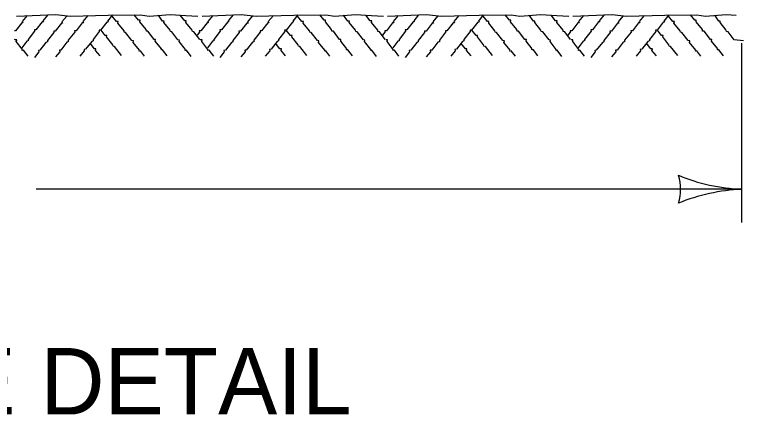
# Model space of a CAD drawing. Extents: x 49991.4 to 50022.1, y 49985 to 50011.4.
# Drawn here: x 50005.452 to 50006.329, y 49996.72 to 49997.202 of the extents above; entities that cross this region are included whole.
import ezdxf

# ---------------------------------------------------------------- set-up
doc = ezdxf.new("R2010")
doc.units = 0
for name, color, linetype in [('Level 1', 7, 'Continuous'), ('Level 2', 7, 'Continuous'), ('Level 3', 7, 'Continuous')]:
    doc.layers.add(name, color=color, linetype=linetype)

msp = doc.modelspace()

# ---------------------------------------------------------------- linework, layer by layer
at = {"layer": 'Level 1'}
for points in [[(50005.4675, 49997.2012), (50005.4615, 49997.1941), (50005.4623, 49997.1926), (50005.4609, 49997.1926), (50005.4535, 49997.183), (50005.4523, 49997.183)], [(50005.4545, 49997.2006), (50005.5017, 49997.2025), (50005.5195, 49997.2004), (50005.5649, 49997.2019), (50005.6037, 49997.2022), (50005.6141, 49997.2007), (50005.6393, 49997.2025), (50005.6584, 49997.2013), (50005.6729, 49997.2006)], [(50005.4921, 49997.202), (50005.4863, 49997.195), (50005.4869, 49997.1936), (50005.4855, 49997.1936), (50005.4779, 49997.184), (50005.4761, 49997.184), (50005.4763, 49997.1824), (50005.4687, 49997.1726), (50005.4687, 49997.171), (50005.467, 49997.1704), (50005.461, 49997.1626)], [(50005.5149, 49997.2004), (50005.5091, 49997.1936), (50005.5099, 49997.1923), (50005.5085, 49997.1923), (50005.5011, 49997.1827), (50005.4993, 49997.1827), (50005.4994, 49997.181), (50005.4917, 49997.1713), (50005.4917, 49997.1696), (50005.4899, 49997.1689), (50005.4827, 49997.1596), (50005.4809, 49997.1593), (50005.4814, 49997.1576), (50005.476, 49997.151)], [(50005.5405, 49997.2012), (50005.5345, 49997.1941), (50005.5353, 49997.1926), (50005.5337, 49997.1926), (50005.5264, 49997.183), (50005.5243, 49997.183), (50005.5247, 49997.1812), (50005.5169, 49997.1718), (50005.5169, 49997.1698), (50005.5153, 49997.1692), (50005.5079, 49997.1598), (50005.5061, 49997.1598), (50005.5065, 49997.1578), (50005.5013, 49997.1515)], [(50005.5699, 49997.202), (50005.5641, 49997.1947), (50005.5648, 49997.1935), (50005.5633, 49997.1935), (50005.5558, 49997.1839), (50005.554, 49997.1839), (50005.5541, 49997.1822), (50005.5467, 49997.1726), (50005.5467, 49997.1707), (50005.545, 49997.1702), (50005.5377, 49997.1608), (50005.5359, 49997.1606), (50005.5361, 49997.1587), (50005.5309, 49997.1524)], [(50005.6085, 49997.1524), (50005.6037, 49997.1587), (50005.6021, 49997.1584), (50005.6025, 49997.1598), (50005.5948, 49997.169), (50005.5954, 49997.171), (50005.5935, 49997.1712), (50005.5859, 49997.1808), (50005.5841, 49997.1812), (50005.584, 49997.183), (50005.5765, 49997.1922), (50005.5767, 49997.1941), (50005.575, 49997.1941), (50005.5697, 49997.2006)], [(50005.6357, 49997.153), (50005.6303, 49997.1602), (50005.6289, 49997.1599), (50005.629, 49997.1612), (50005.6215, 49997.1706), (50005.6219, 49997.1725), (50005.6201, 49997.1726), (50005.6125, 49997.1824), (50005.6109, 49997.1827), (50005.6105, 49997.1845), (50005.6029, 49997.1936), (50005.6033, 49997.1956), (50005.6014, 49997.1956), (50005.5963, 49997.202)], [(50005.6649, 49997.1522), (50005.6591, 49997.1596), (50005.6577, 49997.1592), (50005.6578, 49997.1605), (50005.6503, 49997.1701), (50005.6507, 49997.1718), (50005.6489, 49997.172), (50005.6413, 49997.1816), (50005.6397, 49997.1821), (50005.6395, 49997.1838), (50005.6319, 49997.193), (50005.6321, 49997.1947), (50005.6303, 49997.1947), (50005.6253, 49997.2016)], [(50005.6753, 49997.1726), (50005.6681, 49997.1816), (50005.6663, 49997.1822), (50005.6661, 49997.1839), (50005.6585, 49997.193), (50005.6589, 49997.195), (50005.6571, 49997.195), (50005.6517, 49997.2019)], [(50005.6908, 49997.2012), (50005.6848, 49997.1941), (50005.6854, 49997.1926), (50005.6841, 49997.1926), (50005.6765, 49997.183), (50005.6757, 49997.183)], [(50005.6779, 49997.2006), (50005.725, 49997.2025), (50005.7429, 49997.2004), (50005.7883, 49997.2019), (50005.8269, 49997.2022), (50005.8375, 49997.2007), (50005.8624, 49997.2025), (50005.8817, 49997.2013), (50005.8963, 49997.2006)], [(50005.7154, 49997.202), (50005.7094, 49997.195), (50005.7101, 49997.1936), (50005.7087, 49997.1936), (50005.7013, 49997.184), (50005.6993, 49997.184), (50005.6997, 49997.1824), (50005.692, 49997.1726), (50005.692, 49997.171), (50005.6903, 49997.1704), (50005.6843, 49997.1626)], [(50005.7381, 49997.2004), (50005.7325, 49997.1936), (50005.7333, 49997.1923), (50005.7317, 49997.1923), (50005.7243, 49997.1827), (50005.7223, 49997.1827), (50005.7227, 49997.181), (50005.7149, 49997.1713), (50005.7149, 49997.1696), (50005.7133, 49997.1689), (50005.7059, 49997.1596), (50005.7041, 49997.1593), (50005.7045, 49997.1576), (50005.6993, 49997.151)], [(50005.7639, 49997.2012), (50005.7575, 49997.1941), (50005.7583, 49997.1926), (50005.7569, 49997.1926), (50005.7495, 49997.183), (50005.7477, 49997.183), (50005.7478, 49997.1812), (50005.7401, 49997.1718), (50005.7401, 49997.1698), (50005.7385, 49997.1692), (50005.7311, 49997.1598), (50005.7295, 49997.1598), (50005.7298, 49997.1578), (50005.7244, 49997.1515)], [(50005.7933, 49997.202), (50005.7873, 49997.1947), (50005.788, 49997.1935), (50005.7867, 49997.1935), (50005.7791, 49997.1839), (50005.7773, 49997.1839), (50005.7775, 49997.1822), (50005.7699, 49997.1726), (50005.7699, 49997.1707), (50005.7681, 49997.1702), (50005.7609, 49997.1608), (50005.7591, 49997.1606), (50005.7593, 49997.1587), (50005.7539, 49997.1524)], [(50005.8317, 49997.1524), (50005.827, 49997.1587), (50005.8255, 49997.1584), (50005.8257, 49997.1598), (50005.8181, 49997.169), (50005.8185, 49997.171), (50005.8167, 49997.1712), (50005.8091, 49997.1808), (50005.8075, 49997.1812), (50005.8071, 49997.183), (50005.7995, 49997.1922), (50005.8, 49997.1941), (50005.7981, 49997.1941), (50005.7929, 49997.2006)], [(50005.8589, 49997.153), (50005.8534, 49997.1602), (50005.8519, 49997.1599), (50005.8523, 49997.1612), (50005.8449, 49997.1706), (50005.8451, 49997.1725), (50005.8433, 49997.1726), (50005.8359, 49997.1824), (50005.8341, 49997.1827), (50005.8337, 49997.1845), (50005.8263, 49997.1936), (50005.8264, 49997.1956), (50005.8247, 49997.1956), (50005.8195, 49997.202)], [(50005.8879, 49997.1522), (50005.8823, 49997.1596), (50005.8809, 49997.1592), (50005.8811, 49997.1605), (50005.8735, 49997.1701), (50005.8739, 49997.1718), (50005.8721, 49997.172), (50005.8647, 49997.1816), (50005.8629, 49997.1821), (50005.8625, 49997.1838), (50005.8551, 49997.193), (50005.8555, 49997.1947), (50005.8535, 49997.1947), (50005.8483, 49997.2016)], [(50005.8984, 49997.1726), (50005.8913, 49997.1816), (50005.8895, 49997.1822), (50005.8894, 49997.1839), (50005.8817, 49997.193), (50005.8821, 49997.195), (50005.8803, 49997.195), (50005.875, 49997.2019)], [(50005.914, 49997.2012), (50005.908, 49997.1941), (50005.9087, 49997.1926), (50005.9073, 49997.1926), (50005.8997, 49997.183), (50005.8989, 49997.183)], [(50005.9009, 49997.2006), (50005.9481, 49997.2025), (50005.9659, 49997.2004), (50006.0115, 49997.2019), (50006.0499, 49997.2022), (50006.0605, 49997.2007), (50006.0855, 49997.2025), (50006.1048, 49997.2013), (50006.1195, 49997.2006)], [(50005.9385, 49997.202), (50005.9327, 49997.195), (50005.9333, 49997.1936), (50005.932, 49997.1936), (50005.9245, 49997.184), (50005.9225, 49997.184), (50005.9229, 49997.1824), (50005.9151, 49997.1726), (50005.9151, 49997.171), (50005.9134, 49997.1704), (50005.9074, 49997.1626)], [(50005.9613, 49997.2004), (50005.9555, 49997.1936), (50005.9563, 49997.1923), (50005.9548, 49997.1923), (50005.9475, 49997.1827), (50005.9457, 49997.1827), (50005.9458, 49997.181), (50005.9381, 49997.1713), (50005.9381, 49997.1696), (50005.9365, 49997.1689), (50005.9291, 49997.1596), (50005.9273, 49997.1593), (50005.9277, 49997.1576), (50005.9224, 49997.151)], [(50005.9869, 49997.2012), (50005.9809, 49997.1941), (50005.9817, 49997.1926), (50005.9801, 49997.1926), (50005.9727, 49997.183), (50005.9709, 49997.183), (50005.971, 49997.1812), (50005.9635, 49997.1718), (50005.9635, 49997.1698), (50005.9615, 49997.1692), (50005.9545, 49997.1598), (50005.9525, 49997.1598), (50005.953, 49997.1578), (50005.9477, 49997.1515)], [(50006.0163, 49997.202), (50006.0105, 49997.1947), (50006.0113, 49997.1935), (50006.0099, 49997.1935), (50006.0023, 49997.1839), (50006.0004, 49997.1839), (50006.0005, 49997.1822), (50005.9929, 49997.1726), (50005.9929, 49997.1707), (50005.9914, 49997.1702), (50005.9841, 49997.1608), (50005.9823, 49997.1606), (50005.9825, 49997.1587), (50005.9773, 49997.1524)], [(50006.055, 49997.1524), (50006.0501, 49997.1587), (50006.0485, 49997.1584), (50006.0489, 49997.1598), (50006.0413, 49997.169), (50006.0418, 49997.171), (50006.04, 49997.1712), (50006.0323, 49997.1808), (50006.0305, 49997.1812), (50006.0304, 49997.183), (50006.0229, 49997.1922), (50006.0231, 49997.1941), (50006.0213, 49997.1941), (50006.0161, 49997.2006)], [(50006.0821, 49997.153), (50006.0767, 49997.1602), (50006.0749, 49997.1599), (50006.0754, 49997.1612), (50006.0679, 49997.1706), (50006.0683, 49997.1725), (50006.0664, 49997.1726), (50006.0589, 49997.1824), (50006.0573, 49997.1827), (50006.0569, 49997.1845), (50006.0493, 49997.1936), (50006.0497, 49997.1956), (50006.0478, 49997.1956), (50006.0429, 49997.202)], [(50006.1109, 49997.1522), (50006.1055, 49997.1596), (50006.1041, 49997.1592), (50006.1043, 49997.1605), (50006.0969, 49997.1701), (50006.0971, 49997.1718), (50006.0955, 49997.172), (50006.0879, 49997.1816), (50006.0861, 49997.1821), (50006.0857, 49997.1838), (50006.0783, 49997.193), (50006.0785, 49997.1947), (50006.0767, 49997.1947), (50006.0717, 49997.2016)], [(50006.1215, 49997.1726), (50006.1145, 49997.1816), (50006.1127, 49997.1822), (50006.1125, 49997.1839), (50006.1049, 49997.193), (50006.1053, 49997.195), (50006.1033, 49997.195), (50006.0981, 49997.2019)], [(50006.1371, 49997.2012), (50006.1311, 49997.1941), (50006.1318, 49997.1926), (50006.1303, 49997.1926), (50006.1229, 49997.183), (50006.1221, 49997.183)], [(50006.1241, 49997.2006), (50006.1714, 49997.2025), (50006.1889, 49997.2004), (50006.2349, 49997.2019), (50006.2733, 49997.2022), (50006.2839, 49997.2007), (50006.3088, 49997.2025), (50006.3207, 49997.2018)], [(50006.1618, 49997.202), (50006.1558, 49997.195), (50006.1565, 49997.1936), (50006.1551, 49997.1936), (50006.1479, 49997.184), (50006.1457, 49997.184), (50006.1461, 49997.1824), (50006.1384, 49997.1726), (50006.1384, 49997.171), (50006.1367, 49997.1704), (50006.1305, 49997.1626)], [(50006.1843, 49997.2004), (50006.1789, 49997.1936), (50006.1795, 49997.1923), (50006.1781, 49997.1923), (50006.1707, 49997.1827), (50006.1689, 49997.1827), (50006.169, 49997.181), (50006.1613, 49997.1713), (50006.1613, 49997.1696), (50006.1599, 49997.1689), (50006.1523, 49997.1596), (50006.1505, 49997.1593), (50006.151, 49997.1576), (50006.1457, 49997.151)], [(50006.2099, 49997.2012), (50006.2039, 49997.1941), (50006.2049, 49997.1926), (50006.2033, 49997.1926), (50006.196, 49997.183), (50006.1941, 49997.183), (50006.1943, 49997.1812), (50006.1865, 49997.1718), (50006.1865, 49997.1698), (50006.1849, 49997.1692), (50006.1775, 49997.1598), (50006.1757, 49997.1598), (50006.1761, 49997.1578), (50006.1708, 49997.1515)], [(50006.2397, 49997.202), (50006.2337, 49997.1947), (50006.2344, 49997.1935), (50006.2329, 49997.1935), (50006.2255, 49997.1839), (50006.2235, 49997.1839), (50006.2239, 49997.1822), (50006.2163, 49997.1726), (50006.2163, 49997.1707), (50006.2145, 49997.1702), (50006.2073, 49997.1608), (50006.2053, 49997.1606), (50006.2057, 49997.1587), (50006.2005, 49997.1524)], [(50006.2781, 49997.1524), (50006.2734, 49997.1587), (50006.2717, 49997.1584), (50006.2721, 49997.1598), (50006.2645, 49997.169), (50006.265, 49997.171), (50006.2631, 49997.1712), (50006.2555, 49997.1808), (50006.2539, 49997.1812), (50006.2535, 49997.183), (50006.2459, 49997.1922), (50006.2464, 49997.1941), (50006.2445, 49997.1941), (50006.2395, 49997.2006)], [(50006.3055, 49997.153), (50006.2998, 49997.1602), (50006.2983, 49997.1599), (50006.2985, 49997.1612), (50006.2909, 49997.1706), (50006.2915, 49997.1725), (50006.2897, 49997.1726), (50006.2823, 49997.1824), (50006.2803, 49997.1827), (50006.2801, 49997.1845), (50006.2727, 49997.1936), (50006.2728, 49997.1956), (50006.271, 49997.1956), (50006.2659, 49997.202)], [(50006.3295, 49997.1709), (50006.3185, 49997.172), (50006.3111, 49997.1816), (50006.3093, 49997.1821), (50006.3089, 49997.1838), (50006.3015, 49997.193), (50006.3017, 49997.1947), (50006.2998, 49997.1947), (50006.2949, 49997.2016)], [(50005.581, 49997.1532), (50005.5723, 49997.1642), (50005.5707, 49997.1646), (50005.5705, 49997.1662), (50005.5629, 49997.1755), (50005.5631, 49997.1773), (50005.5613, 49997.1773), (50005.5563, 49997.1839)], [(50005.6755, 49997.183), (50005.6745, 49997.183), (50005.6747, 49997.1812), (50005.6719, 49997.1778)], [(50005.8041, 49997.1532), (50005.7957, 49997.1642), (50005.7939, 49997.1646), (50005.7935, 49997.1662), (50005.7861, 49997.1755), (50005.7863, 49997.1773), (50005.7844, 49997.1773), (50005.7793, 49997.1839)], [(50005.8985, 49997.183), (50005.8977, 49997.183), (50005.8978, 49997.1812), (50005.8949, 49997.1778)], [(50006.0274, 49997.1532), (50006.0189, 49997.1642), (50006.0171, 49997.1646), (50006.0167, 49997.1662), (50006.0093, 49997.1755), (50006.0095, 49997.1773), (50006.0077, 49997.1773), (50006.0027, 49997.1839)], [(50006.1217, 49997.183), (50006.121, 49997.183), (50006.1211, 49997.1812), (50006.1183, 49997.1778)], [(50006.2505, 49997.1532), (50006.2419, 49997.1642), (50006.2403, 49997.1646), (50006.2399, 49997.1662), (50006.2323, 49997.1755), (50006.2327, 49997.1773), (50006.2308, 49997.1773), (50006.2259, 49997.1839)], [(50005.4685, 49997.1524), (50005.4629, 49997.1598), (50005.4615, 49997.1593), (50005.4617, 49997.1606), (50005.4543, 49997.1701), (50005.4549, 49997.1719), (50005.4529, 49997.172), (50005.4523, 49997.1726)], [(50005.6919, 49997.1524), (50005.6863, 49997.1598), (50005.6847, 49997.1593), (50005.6849, 49997.1606), (50005.6775, 49997.1701), (50005.6779, 49997.1719), (50005.6759, 49997.172), (50005.6757, 49997.1726)], [(50005.9149, 49997.1524), (50005.9095, 49997.1598), (50005.908, 49997.1593), (50005.9081, 49997.1606), (50005.9007, 49997.1701), (50005.9009, 49997.1719), (50005.8993, 49997.172), (50005.8989, 49997.1726)], [(50006.1383, 49997.1524), (50006.1325, 49997.1598), (50006.1311, 49997.1593), (50006.1315, 49997.1606), (50006.124, 49997.1701), (50006.1243, 49997.1719), (50006.1225, 49997.172), (50006.1221, 49997.1726)], [(50005.5553, 49997.1527), (50005.5498, 49997.1593), (50005.5499, 49997.1612), (50005.5483, 49997.1612), (50005.5431, 49997.168)], [(50005.7784, 49997.1527), (50005.773, 49997.1593), (50005.7733, 49997.1612), (50005.7715, 49997.1612), (50005.7664, 49997.168)], [(50006.0017, 49997.1527), (50005.9963, 49997.1593), (50005.9965, 49997.1612), (50005.9949, 49997.1612), (50005.9895, 49997.168)], [(50006.2248, 49997.1527), (50006.2194, 49997.1593), (50006.2199, 49997.1612), (50006.2179, 49997.1612), (50006.2127, 49997.168)]]:
    msp.add_lwpolyline(points, dxfattribs=at)
at = {"layer": 'Level 3'}
for p, q in [((50006.3273, 49997.168), (50006.3273, 49996.9522)), ((50006.3273, 49996.9922), (50005.47823, 49996.9922))]:
    msp.add_line(p, q, dxfattribs=at)
for centre, radius, start, end in [((50006.33646, 49997.21433), 0.22232, 247.45601, 267.63952), ((50006.19909, 49996.9922), 0.05477, 342.13882, 17.86118), ((50006.33879, 49996.75949), 0.233, 92.82731, 112.07716)]:
    msp.add_arc(centre, radius, start, end, dxfattribs=at)

# ---------------------------------------------------------------- texts
at = {"layer": 'Level 2'}
msp.add_text('SLOPE DETAIL', height=0.08, dxfattribs=at).set_placement((50005.0967, 49996.72095))

doc.saveas('drawing.dxf')
